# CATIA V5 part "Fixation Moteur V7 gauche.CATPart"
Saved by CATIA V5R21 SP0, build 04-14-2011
Part number: MOTEURGAUCHE
Bounding box of the stored display mesh (mm): x -4.2 to 4.2, y -40 to 0, z -20 to 40
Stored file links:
  C:\Users\2027.DESARCY-LEMIE30\Desktop\V15(20.03.2023)\Fixation Moteur V7 gauche.CATPart
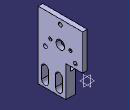
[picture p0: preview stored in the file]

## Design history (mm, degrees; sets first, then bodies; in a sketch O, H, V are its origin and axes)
Body1 (main body)
  Sketch1 on yz-plane, origin (0, 0, 0), H (0, 1, 0), V (0, 0, 1)
    line L1 (-40, 40) -> (0, 40)
    line L2 (0, 40) -> (0, 0)
    line L3 (0, 0) -> (-40, 0)
    line L4 (-40, 0) -> (-40, 40)
    point P3 (0, 0)
    length L4 = 40
    length L1 = 40
    horizontal: L1 H, L3 H
    vertical: L2 V, L4 V
    coincidence: P3 O
  Pad1: profile Sketch1, direction (1, 0, 0), length 4.2
  Sketch2 on end face of Pad1, origin (4.2, 0, 0), H (0, 1, 0), V (0, 0, 1)
    point P1 (-40, 0)
    line L1 (-40, 0) -> (-15, 0)
    line L2 (-15, 0) -> (-15, -20)
    line L3 (-15, -20) -> (-40, -20)
    line L4 (-40, -20) -> (-40, 0)
    reference projected point E1 (-40, 0) from vertex [face of Pad1 from Sketch1.L3 | end face of Pad1 | face of Pad1 from Sketch1.L4]
    length L2 = 20
    length L3 = 25
    horizontal: L1 H, L3 H
    vertical: L2 V, L4 V
    coincidence: P1 E1
  Pad2: profile Sketch2, direction (-1, 0, 0), length 8.4
  Sketch3 on end face of Pad2, origin (-4.2, 0, 0), H (0, -1, 0), V (0, 0, 1)
    point P1 (18.15, -5)
    line L1 (24.35, -5) -> (24.35, -15)
    line L2 (18.15, -15) -> (18.15, -5)
    point P2 (24.35, -5)
    point P3 (24.35, -15)
    point P4 (18.15, -15)
    axis line L3 (27.5, 2.3624) -> (27.5, -21.6714)
    reference projected line E1 (40, 0) -> (40, -20) from edge [end face of Pad2 | face of Pad2 from Sketch2.L4]
    arc A1 centre (21.25, -5) radius 3.1 from (24.35, -5) to (18.15, -5) ccw
    point P8 (10.7649, -15.4491)
    arc A2 centre (21.25, -15) radius 3.1 from (18.15, -15) to (24.35, -15) ccw
    point P9 (21.25, -15)
    point P10 (18.15, -15)
    point P11 (24.35, -15)
    point P12 (36.85, -5)
    point P13 (36.85, -15)
    line L4 (36.85, -15) -> (36.85, -5)
    point P14 (30.65, -5)
    arc A3 centre (33.75, -5) radius 3.1 from (30.65, -5) to (36.85, -5) cw
    point P16 (30.65, -15)
    line L5 (30.65, -5) -> (30.65, -15)
    point P17 (30.65, -15)
    point P18 (36.85, -15)
    point P19 (33.75, -15)
    arc A4 centre (33.75, -15) radius 3.1 from (36.85, -15) to (30.65, -15) cw
    reference projected line E2 (40, -20) -> (15, -20) from edge [end face of Pad2 | face of Pad2 from Sketch2.L3]
    distance L3 E1 = 12.5
    radius A1 = 3.1
    distance P9 P19 = 12.5
    length L4 = 10
    distance A4 E2 = 1.9
    vertical: L1 V, L2 V, L3 V
    tangency: A1 L1, A1 L2, A2 L1, A2 L2
    coincidence: P4 A2, L1 P11, L2 P10, P3 P11, P4 P10, P13 P18, P16 P17
    symmetry: P1 P12 L3, P4 P13 L3, L2 L4 L3, P2 P14 L3, A1 A3 L3, P3 P16 L3, L1 L5 L3, P11 P17 L3, P10 P18 L3, A2 A4 L3
  Pocket1: profile Sketch3, direction (1, 0, 0), through (limit type 3)
  Sketch4 on start face of Pad1, origin (0, 0, 0), H (0, -1, 0), V (0, 0, 1)
    construction line L1 (0, 20) -> (40, 20)
    point P1 (0, 20)
    point P2 (40, 20)
    reference projected line E1 (0, 40) -> (40, 40) from edge [start face of Pad1 | face of Pad1 from Sketch1.L1]
    reference projected line E2 (0, 0) -> (0, 40) from edge [start face of Pad1 | face of Pad2]
    reference projected line E3 (40, 40) -> (40, 0) from edge [start face of Pad1 | face of Pad1 from Sketch1.L4]
    construction line L2 (20, 40) -> (20, 0)
    point P3 (20, 40)
    point P4 (20, 0)
    reference projected line E4 (0, 40) -> (40, 40) from edge [start face of Pad1 | face of Pad1 from Sketch1.L1]
    reference projected line E5 (40, 0) -> (0, 0) from edge [start face of Pad1 | face of Pad1 from Sketch1.L3]
    reference projected line E6 (40, 40) -> (40, 0) from edge [start face of Pad1 | face of Pad1 from Sketch1.L4]
    circle A1 centre (20, 20) radius 4
    point P5 (20, 20)
    construction line L3 (20, 20) -> (0, 8.453)
    point P6 (0, 8.453)
    axis line L4 (20, 20) -> (40, 8.453)
    point P7 (40, 8.453)
    reference projected line E7 (40, 40) -> (40, 0) from edge [start face of Pad1 | face of Pad1 from Sketch1.L4]
    circle A2 centre (20, 35.5885) radius 1.75
    point P8 (20, 35.5885)
    point P9 (33.5, 12.2058)
    circle A3 centre (33.5, 12.2058) radius 1.75
    point P10 (6.5, 12.2058)
    circle A4 centre (6.5, 12.2058) radius 1.75
    distance E1 L1 = 20
    distance L2 E6 = 20
    radius A1 = 4
    angle L3 L2 = 120
    angle L2 L4 = 120
    radius A2 = 1.75
    distance P9 P10 = 27
    horizontal: L1 H
    coincidence: P1 E2, P2 E3, E4 P3, P4 E5, P5 L2, P6 V, P7 E7, P8 L2
    vertical: L2 V
    midpoint: P5 L2
    symmetry: A2 A3 L3, A3 A4 L2
  Pocket2: profile Sketch4, direction (1, 0, 0), through (limit type 3)
  Sketch5 on start face of Pad1, origin (0, -33.6663, 26.8229), H (0, 1, 0), V (0, 0, -1)
    point P1 (22.6663, 6.8229)
    axis line L1 (13.6663, 6.8229) -> (56.6573, 6.8229)
    point P2 (13.6663, 6.8229)
    reference projected circle E1 centre (13.6663, 6.8229) radius 4 from edge [start face of Pad1 | face of Pocket2 from Sketch4.A1]
    distance P2 P1 = 9
    horizontal: L1 H
    concentricity: P2 E1
    coincidence: P1 L1
  Hole1: placed by Sketch5, at (0, -11, 20) direction (1, 0, 0), diameter 3, through (limit type 6), counterbore diameter 6, counterbore depth 3
  RectPattern1: of Hole1, direction 1 instances 2, spacing 18, along face of Pad1 from Sketch1.L1 reversed
  Sketch6 on start face of Pad1, origin (0, 0, 0), H (0, -1, 0), V (0, 0, 1)
    line L1 (0, 0) -> (15, 0)
    line L2 (15, 0) -> (15, 8)
    line L3 (15, 8) -> (0, 8)
    line L4 (0, 8) -> (0, 0)
    reference projected line E1 (15, -20) -> (15, 0) from edge [end face of Pad2 | face of Pad2 from Sketch2.L2]
    length L2 = 8
    horizontal: L1 H, L3 H
    vertical: L2 V, L4 V
    coincidence: L2 E1
  Pocket3: profile Sketch6, direction (1, 0, 0), through (limit type 3)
